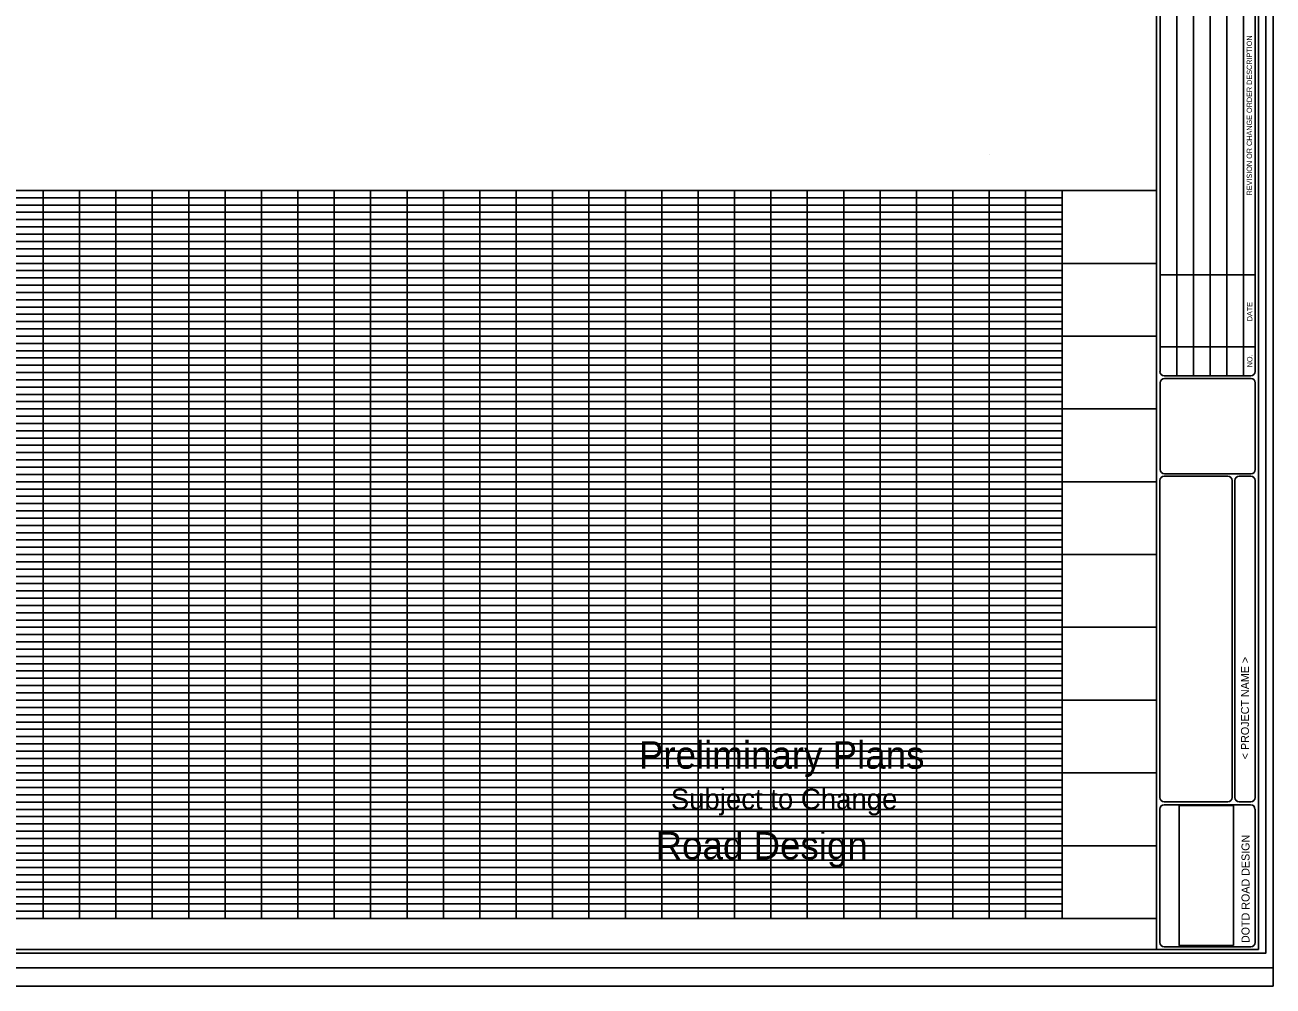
# Model space of a CAD drawing. Extents: x -1.93 to 2.83, y -1.79 to 1.85.
# Drawn here: x 1.404 to 2.833, y 0 to 1.1 of the extents above; entities that cross this region are included whole.
import ezdxf

# ---------------------------------------------------------------- set-up
doc = ezdxf.new("R2010")
doc.units = 0
for name, color, linetype in [('Border Info', 7, 'Continuous'), ('File Info', 7, 'Continuous'), ('Plot Border', 7, 'Continuous'), ('Plot Border 2', 7, 'Continuous'), ('Profile Grid', 7, 'Continuous'), ('Seal', 7, 'Continuous'), ('Sheet Border', 7, 'Continuous')]:
    doc.layers.add(name, color=color, linetype=linetype)

msp = doc.modelspace()

# ---------------------------------------------------------------- linework, layer by layer
at = {"layer": 'File Info'}
msp.add_line((2.5083, 0.9523), (2.5083, 0.9523), dxfattribs=at)
at = {"layer": 'Plot Border'}
for points in [[(0, 1.8333), (2.8333, 1.8333), (2.8333, 0), (0, 0)], [(2.825, 1.7958), (0.075, 1.7958), (0.075, 0.0375), (2.825, 0.0375)]]:
    msp.add_lwpolyline(points, close=True, dxfattribs=at)
at = {"layer": 'Plot Border 2'}
msp.add_lwpolyline([(0, 1.8125), (2.8333, 1.8125), (2.8333, 0.0208), (0, 0.0208)], close=True, dxfattribs=at)
at = {"layer": 'Profile Grid'}
for p, q in [((2.7, 0.9106), (0.8167, 0.9106)), ((0.925, 0.9022), (2.5917, 0.9022)), ((1.425, 0.0772), (1.425, 0.9106)), ((1.4667, 0.0772), (1.4667, 0.9106)), ((1.5083, 0.0772), (1.5083, 0.9106)), ((1.55, 0.0772), (1.55, 0.9106)), ((1.5917, 0.0772), (1.5917, 0.9106)), ((1.6333, 0.0772), (1.6333, 0.9106)), ((1.675, 0.0772), (1.675, 0.9106)), ((1.7167, 0.0772), (1.7167, 0.9106)), ((1.7583, 0.0772), (1.7583, 0.9106)), ((1.8, 0.0772), (1.8, 0.9106)), ((1.8417, 0.0772), (1.8417, 0.9106)), ((1.8833, 0.0772), (1.8833, 0.9106)), ((1.925, 0.0772), (1.925, 0.9106)), ((1.9667, 0.0772), (1.9667, 0.9106)), ((2.0083, 0.0772), (2.0083, 0.9106)), ((2.05, 0.0772), (2.05, 0.9106)), ((2.0917, 0.0772), (2.0917, 0.9106)), ((2.1333, 0.0772), (2.1333, 0.9106)), ((2.175, 0.0772), (2.175, 0.9106)), ((2.2167, 0.0772), (2.2167, 0.9106)), ((2.2583, 0.0772), (2.2583, 0.9106)), ((2.3, 0.0772), (2.3, 0.9106)), ((2.3417, 0.0772), (2.3417, 0.9106)), ((2.3833, 0.0772), (2.3833, 0.9106)), ((2.425, 0.0772), (2.425, 0.9106)), ((2.4667, 0.0772), (2.4667, 0.9106)), ((2.5083, 0.0772), (2.5083, 0.9106)), ((2.55, 0.0772), (2.55, 0.9106)), ((2.5917, 0.0772), (2.5917, 0.9106)), ((0.925, 0.8939), (2.5917, 0.8939)), ((0.925, 0.8856), (2.5917, 0.8856)), ((0.925, 0.8772), (2.5917, 0.8772)), ((0.925, 0.8689), (2.5917, 0.8689)), ((0.925, 0.8606), (2.5917, 0.8606)), ((0.925, 0.8522), (2.5917, 0.8522)), ((0.925, 0.8439), (2.5917, 0.8439)), ((0.925, 0.8356), (2.5917, 0.8356)), ((0.8167, 0.8272), (2.7, 0.8272)), ((0.925, 0.8189), (2.5917, 0.8189)), ((0.925, 0.8106), (2.5917, 0.8106)), ((0.925, 0.8022), (2.5917, 0.8022)), ((0.925, 0.7939), (2.5917, 0.7939)), ((0.925, 0.7856), (2.5917, 0.7856)), ((0.925, 0.7772), (2.5917, 0.7772)), ((0.925, 0.7689), (2.5917, 0.7689)), ((0.925, 0.7606), (2.5917, 0.7606)), ((0.8167, 0.7439), (2.7, 0.7439)), ((0.925, 0.7522), (2.5917, 0.7522)), ((0.925, 0.7356), (2.5917, 0.7356)), ((0.925, 0.7272), (2.5917, 0.7272)), ((0.925, 0.7189), (2.5917, 0.7189)), ((0.925, 0.7106), (2.5917, 0.7106)), ((0.925, 0.7022), (2.5917, 0.7022)), ((0.925, 0.6939), (2.5917, 0.6939)), ((0.925, 0.6856), (2.5917, 0.6856)), ((0.925, 0.6772), (2.5917, 0.6772)), ((0.8167, 0.6606), (2.7, 0.6606)), ((0.925, 0.6689), (2.5917, 0.6689)), ((0.925, 0.6522), (2.5917, 0.6522)), ((0.925, 0.6439), (2.5917, 0.6439)), ((0.925, 0.6356), (2.5917, 0.6356)), ((0.925, 0.6272), (2.5917, 0.6272)), ((0.925, 0.6189), (2.5917, 0.6189)), ((0.925, 0.6106), (2.5917, 0.6106)), ((0.925, 0.6022), (2.5917, 0.6022)), ((0.925, 0.5939), (2.5917, 0.5939)), ((0.8167, 0.5772), (2.7, 0.5772)), ((0.925, 0.5856), (2.5917, 0.5856)), ((0.925, 0.5689), (2.5917, 0.5689)), ((0.925, 0.5606), (2.5917, 0.5606)), ((0.925, 0.5522), (2.5917, 0.5522)), ((0.925, 0.5439), (2.5917, 0.5439)), ((0.925, 0.5356), (2.5917, 0.5356)), ((0.925, 0.5272), (2.5917, 0.5272)), ((0.925, 0.5189), (2.5917, 0.5189)), ((0.925, 0.5106), (2.5917, 0.5106)), ((0.925, 0.5022), (2.5917, 0.5022)), ((0.8167, 0.4939), (2.7, 0.4939)), ((0.925, 0.4856), (2.5917, 0.4856)), ((0.925, 0.4772), (2.5917, 0.4772)), ((0.925, 0.4689), (2.5917, 0.4689)), ((0.925, 0.4606), (2.5917, 0.4606)), ((0.925, 0.4522), (2.5917, 0.4522)), ((0.925, 0.4439), (2.5917, 0.4439)), ((0.925, 0.4356), (2.5917, 0.4356)), ((0.925, 0.4272), (2.5917, 0.4272)), ((0.925, 0.4189), (2.5917, 0.4189)), ((0.8167, 0.4106), (2.7, 0.4106)), ((0.925, 0.4022), (2.5917, 0.4022)), ((0.925, 0.3939), (2.5917, 0.3939)), ((0.925, 0.3856), (2.5917, 0.3856)), ((0.925, 0.3772), (2.5917, 0.3772)), ((0.925, 0.3689), (2.5917, 0.3689)), ((0.925, 0.3606), (2.5917, 0.3606)), ((0.925, 0.3522), (2.5917, 0.3522)), ((0.925, 0.3439), (2.5917, 0.3439)), ((0.925, 0.3356), (2.5917, 0.3356)), ((0.8167, 0.3272), (2.7, 0.3272)), ((0.925, 0.3189), (2.5917, 0.3189)), ((0.925, 0.3106), (2.5917, 0.3106)), ((0.925, 0.3022), (2.5917, 0.3022)), ((0.925, 0.2939), (2.5917, 0.2939)), ((0.925, 0.2856), (2.5917, 0.2856)), ((0.925, 0.2772), (2.5917, 0.2772)), ((0.925, 0.2689), (2.5917, 0.2689)), ((0.925, 0.2606), (2.5917, 0.2606)), ((0.8167, 0.2439), (2.7, 0.2439)), ((0.925, 0.2522), (2.5917, 0.2522)), ((0.925, 0.2356), (2.5917, 0.2356)), ((0.925, 0.2272), (2.5917, 0.2272)), ((0.925, 0.2189), (2.5917, 0.2189)), ((0.925, 0.2106), (2.5917, 0.2106)), ((0.925, 0.2022), (2.5917, 0.2022)), ((0.925, 0.1939), (2.5917, 0.1939)), ((0.925, 0.1856), (2.5917, 0.1856)), ((0.925, 0.1772), (2.5917, 0.1772)), ((0.8167, 0.1606), (2.7, 0.1606)), ((0.925, 0.1689), (2.5917, 0.1689)), ((0.925, 0.1522), (2.5917, 0.1522)), ((0.925, 0.1439), (2.5917, 0.1439)), ((0.925, 0.1356), (2.5917, 0.1356)), ((0.925, 0.1272), (2.5917, 0.1272)), ((0.925, 0.1189), (2.5917, 0.1189)), ((0.925, 0.1106), (2.5917, 0.1106)), ((0.925, 0.1022), (2.5917, 0.1022)), ((0.925, 0.0939), (2.5917, 0.0939)), ((0.8167, 0.0772), (2.7, 0.0772)), ((0.925, 0.0856), (2.5917, 0.0856))]:
    msp.add_line(p, q, dxfattribs=at)
at = {"layer": 'Seal'}
msp.add_lwpolyline([(2.7881, 0.0465), (2.7881, 0.2067), (2.7257, 0.2067), (2.7257, 0.0465)], close=True, dxfattribs=at)
at = {"layer": 'Sheet Border'}
for p, q in [((2.7, 1.7917), (2.7, 0.0417)), ((2.8167, 1.7917), (2.8167, 0.0417)), ((2.7039, 1.2619), (2.7039, 0.7034)), ((2.723, 1.2668), (2.723, 0.6985)), ((2.7422, 1.2668), (2.7422, 0.6985)), ((2.7613, 1.2668), (2.7613, 0.6985)), ((2.7805, 1.2668), (2.7805, 0.6985)), ((2.7996, 1.2668), (2.7996, 0.6985)), ((2.8128, 1.2619), (2.8128, 0.7034)), ((2.7039, 0.8141), (2.8128, 0.8141)), ((2.7039, 0.7315), (2.8128, 0.7315)), ((2.7041, 0.6904), (2.7041, 0.5914)), ((2.7088, 0.6985), (2.8079, 0.6985)), ((2.8081, 0.6954), (2.709, 0.6954)), ((2.813, 0.6904), (2.813, 0.5914)), ((2.8081, 0.5864), (2.709, 0.5864)), ((2.7038, 0.5791), (2.7038, 0.216)), ((2.7814, 0.5836), (2.7088, 0.5836)), ((2.7864, 0.5787), (2.7864, 0.2157)), ((2.7897, 0.5791), (2.7897, 0.216)), ((2.8078, 0.5836), (2.7946, 0.5836)), ((2.8128, 0.5787), (2.8128, 0.2157)), ((2.7037, 0.2026), (2.7037, 0.0499)), ((2.8077, 0.2075), (2.7087, 0.2075)), ((2.7814, 0.2107), (2.7088, 0.2107)), ((2.8078, 0.2107), (2.7946, 0.2107)), ((2.8127, 0.2026), (2.8127, 0.0499)), ((2.8079, 0.045), (2.7088, 0.045)), ((0.1917, 0.0417), (2.8167, 0.0417))]:
    msp.add_line(p, q, dxfattribs=at)
for centre, start, end in [((2.7088, 0.7035), 180, 270), ((2.8078, 0.7035), 270, 0), ((2.709, 0.6905), 90, 180), ((2.8081, 0.6905), 0, 90), ((2.709, 0.5914), 180, 270), ((2.8081, 0.5914), 270, 0), ((2.7088, 0.5787), 90, 180), ((2.7814, 0.5787), 0, 90), ((2.7946, 0.5787), 90, 180), ((2.8078, 0.5787), 0, 90), ((2.7088, 0.2157), 180, 270), ((2.7814, 0.2157), 270, 0), ((2.7946, 0.2157), 180, 270), ((2.8078, 0.2157), 270, 0), ((2.7087, 0.2026), 90, 180), ((2.8077, 0.2026), 0, 90), ((2.7088, 0.0499), 180, 270), ((2.8079, 0.0499), 270, 360)]:
    msp.add_arc(centre, 0.00495, start, end, dxfattribs=at)

# ---------------------------------------------------------------- texts
at = {"layer": 'Border Info'}
for s, height, p in [('Preliminary Plans', 0.031438, (2.1071, 0.2487)), ('Subject to Change', 0.023578, (2.1437, 0.2023)), ('  Road Design', 0.031438, (2.1029, 0.1451))]:
    msp.add_text(s, height=height, dxfattribs=at).set_placement(p)
at = {"layer": 'Sheet Border'}
for s, height, p in [('REVISION OR CHANGE ORDER DESCRIPTION', 0.006, (2.8092, 0.9049)), ('DATE', 0.006, (2.8096, 0.7609)), ('NO.', 0.006, (2.8097, 0.7082)), ('               < PROJECT NAME >               ', 0.009167, (2.8058, 0.2085)), (' DOTD ROAD DESIGN', 0.009167, (2.8064, 0.0458))]:
    msp.add_text(s, height=height, rotation=90, dxfattribs=at).set_placement(p)

doc.saveas('drawing.dxf')
